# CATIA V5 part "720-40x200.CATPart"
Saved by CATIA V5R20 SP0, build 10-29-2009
Part number: 720-40x200
Definition: NONE
Nomenclature: 720-40x200
Source: Unknown
Description: 720-40x200
Bounding box of the stored display mesh (mm): x 0 to 200, y -20 to 20, z -20 to 20
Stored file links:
  C:\Users\Utente\Desktop\IO LAVORO\3D X SITO CF\X SITO\720\720-40x200.CATPart

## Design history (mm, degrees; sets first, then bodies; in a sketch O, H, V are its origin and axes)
Body1 "720-40x200" (main body)
  Solid1: solid without history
